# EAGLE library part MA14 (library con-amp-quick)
AMP QUICK CONNECTOR
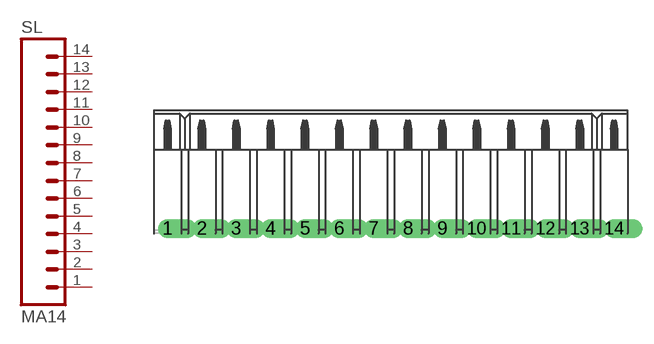
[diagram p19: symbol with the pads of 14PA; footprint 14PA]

Designator prefix SL

## MA14  [14PA]
1  1  pas
2  2  pas
3  3  pas
4  4  pas
5  5  pas
6  6  pas
7  7  pas
8  8  pas
9  9  pas
10  10  pas
11  11  pas
12  12  pas
13  13  pas
14  14  pas

## Footprint 14PA (pad centres in mm)
AMP QUICK CONNECTOR
drill 0.914 offset: 1 -16.51,0; 2 -13.97,0; 3 -11.43,0; 4 -8.89,0; 5 -6.35,0; 6 -3.81,0; 7 -1.27,0; 8 1.27,0; 9 3.81,0; 10 6.35,0; 11 8.89,0; 12 11.43,0; 13 13.97,0; 14 16.51,0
